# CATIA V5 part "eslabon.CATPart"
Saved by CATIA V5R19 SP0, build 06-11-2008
Part number: eslabon
Material "Dull Blue": density 7860 kg/m3, Young's modulus 2e+11 Pa, Poisson ratio 0.266
Bounding box of the stored display mesh (mm): x 189.734 to 215.134, y -352.1 to 352.1, z 11038.485 to 12155.485
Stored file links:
  E:\Luis\Dropbox\3DIT\Parking\planos\cat 3 dit park8\eslabon.CATPart
  E:\Luis\Dropbox\3DIT\Parking\planos\cat 3 dit park8\Eslabon de Cadena.........................................CATProduct
  E:\Luis\Dropbox\3DIT\Parking\planos\cat 3 dit park8\ensamble unico eslabon.CATProduct
  E:\Luis\Dropbox\3DIT\Parking\planos\cat 3 dit park8\Soportecuna.CATProduct
  E:\Luis\Dropbox\3DIT\Parking\planos\cat 3 dit park8\ensamble Parking3d.CATProduct
  C:\Program Files (x86)\Dassault Systemes\B19\intel_a\startup\materials\Catalog.CATMaterial
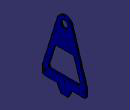
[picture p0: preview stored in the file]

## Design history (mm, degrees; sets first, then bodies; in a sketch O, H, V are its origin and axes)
External parameters (linked from other documents)
  External.P = 625
  External.b1 = 38.1
  External.b2 = 50.8
  External.d2 = 26.4
  External.g = 50.8
  External.LE = 800
Body1 (main body), material "Dull Blue"
  DatumSurface1
  DatumCurve1
  Sketch1, origin (410.9081, 7.5, 9247.3264), H (0, 1, 0), V (0, 0, 1), geometry linked from another document
  Sketch2, origin (410.9081, -1812.5, 6922.3264), H (0, 1, 0), V (0, 0, 1), geometry linked from another document
  Sketch3, origin (313.2342, -1812.5, 4597.3264), H (0, 1, 0), V (0, 0, 1), geometry linked from another document
  Sketch4 on DatumSurface4, origin (202.4342, 0, 0), H (0, 1, 0), V (0, 0, 1)
    point P2 (-312.5, 11235.4854)
    construction line L1 (0, 12035.4854) -> (0, 11235.4854)
    point P3 (0, 11235.4854)
    construction line L2 (0, 12035.4854) -> (-312.5, 11235.4854)
    line L3 (-114.5616, 12071.2016) -> (-352.1, 11309.2854)
    point P4 (-352.1, 11309.2854)
    circle A1 centre (0, 12035.4854) radius 60
    point P5 (0, 11869.2854)
    circle A2 centre (-312.5, 11235.4854) radius 13.2
    point P6 (-307.6972, 11247.7806)
    point P7 (487.5, 10734.2854)
    line L4 (-352.1, 11309.2854) -> (-352.1, 11176.963)
    point P8 (-352.1, 11072.4854)
    point P9 (-352.1, 11159.2854)
    circle A3 centre (0, 11235.4854) radius 9.525
    line L5 (-114.1377, 11159.2854) -> (-334.4223, 11159.2854)
    point P10 (-114.1377, 11159.2854)
    line L6 (-114.1377, 11159.2854) -> (-60, 11038.4854)
    point P11 (-60, 11038.4854)
    line L7 (-60, 11038.4854) -> (0, 11038.4854)
    point P12 (0, 11038.4854)
    line L8 (-352.1, 11176.963) -> (-334.4223, 11159.2854)
    point P13 (-352.1, 11176.963)
    point P14 (-334.4223, 11159.2854)
    construction line L9 (0, 11551.55) -> (0, 12155.4854)
    point P15 (0, 11551.55)
    arc A4 centre (0, 12035.4854) radius 120 from (0, 12155.4854) to (-114.5616, 12071.2016) ccw
    point P16 (0, 12035.4854)
    point P17 (0, 12155.4854)
    point P18 (0, 12155.4854)
    point P19 (-114.5616, 12071.2016)
    point P20 (114.5616, 12071.2016)
    point P21 (0, 12155.4854)
    arc A5 centre (0, 12035.4854) radius 120 from (0, 12155.4854) to (114.5616, 12071.2016) cw
    point P23 (352.1, 11309.2854)
    line L10 (114.5616, 12071.2016) -> (352.1, 11309.2854)
    point P24 (352.1, 11176.963)
    line L11 (352.1, 11309.2854) -> (352.1, 11176.963)
    point P25 (334.4223, 11159.2854)
    point P26 (114.1377, 11159.2854)
    line L12 (114.1377, 11159.2854) -> (334.4223, 11159.2854)
    point P27 (60, 11038.4854)
    line L13 (114.1377, 11159.2854) -> (60, 11038.4854)
    point P28 (0, 11038.4854)
    line L14 (60, 11038.4854) -> (0, 11038.4854)
    circle A6 centre (312.5, 11235.4854) radius 13.2
    line L15 (352.1, 11176.963) -> (334.4223, 11159.2854)
    radius A1 = 60
    radius A2 = 13.2 {= External.d2 /1000/2}
    length L1 = 800 {= External.LE /1000}
    distance P2 L4 = 39.6 {= External.d2 *1.5/1000}
    length L7 = 60
    distance P4 P9 = 150
    distance P10 P9 = 237.9623 (reference)
    angle L4 L8 = 45
    length L8 = 25
    angle L6 L5 = -294.14
    distance L1 P12 = 0
    radius A4 = 120
    distance L14 H = 11038.4854
    distance P11 V = 60 (reference)
    distance L5 P12 = 120.8
    distance P2 L5 = 76.2 {= External.g  *1.5/1000}
    distance L12 P3 = 76.2 {= External.g *1.5/1000}
    radius A3 = 9.525
    distance P2 L1 = 312.5 {= External.P /2/1000}
    vertical: L1 V, L4 V, L9 V
    coincidence: A2 P6, P6 L2, L4 P8, P12 V, L4 P9, L5 P9, P15 L1, L9 L1, P16 L2, P16 L1, L9 P17, P18 A4
    horizontal: L5 H
    tangency: A4 L3
    symmetry: P19 P20 L1, P17 P21 L1, A4 A5 L1, P4 P23 L1, L3 L10 L1, P13 P24 L1, L4 L11 L1, P14 P25 L1, P10 P26 L1, L5 L12 L1, P11 P27 L1, L6 L13 L1, P12 P28 L1, L7 L14 L1, A2 A6 L1, L8 L15 L1
  Pad1: profile Sketch4, direction (1, 0, 0), length 12.7, mirrored extent
  Sketch5, origin (253.2342, 7.5, 9247.3264), H (0, 1, 0), V (0, 0, 1), geometry linked from another document
  Sketch6, origin (253.2342, 7.5, 9247.3264), H (0, 1, 0), V (0, 0, 1), geometry linked from another document
  Sketch7 on start face of Pad1, origin (189.7342, 0, 0), H (0, -1, 0), V (0, 0, 1)
    line L1 (-121.4014, 11674.2854) -> (121.4014, 11674.2854)
    line L2 (164.362, 11642.6789) -> (254.7737, 11352.6789)
    line L3 (211.8131, 11294.2854) -> (-211.8131, 11294.2854)
    line L4 (-254.7737, 11352.6789) -> (-164.362, 11642.6789)
    arc A1 centre (121.4014, 11629.2854) radius 45 from (164.362, 11642.6789) to (121.4014, 11674.2854) ccw
    arc A2 centre (-121.4014, 11629.2854) radius 45 from (-164.362, 11642.6789) to (-121.4014, 11674.2854) cw
    arc A3 centre (-211.8131, 11339.2854) radius 45 from (-254.7737, 11352.6789) to (-211.8131, 11294.2854) ccw
    arc A4 centre (211.8131, 11339.2854) radius 45 from (211.8131, 11294.2854) to (254.7737, 11352.6789) ccw
    construction line L5 (-341.8007, 11342.3207) -> (-146.2032, 11969.7094)
    construction line L6 (-341.8007, 11342.3207) -> (-146.2032, 11969.7094)
    construction line L7 (-273.1, 11161.8476) -> (-273.1, 11259.2854)
    construction line L8 (0, 11038.4854) -> (-60, 11038.4854)
    construction arc A5 centre (0, 11809.2854) radius 120 from (111.9424, 11852.5162) to (-111.9424, 11852.5162) ccw
    point P13 (0, 11209.2854)
    reference projected line E1 (166.7596, 11903.7738) -> (346.5875, 11326.9671) from edge [start face of Pad1 | face of Pad1 from Sketch4.L3]
    reference projected line E2 (282.3223, 11159.2854) -> (114.1377, 11159.2854) from edge [start face of Pad1 | face of Pad1 from Sketch4.L5]
    reference projected line E3 (-351.7709, 11310.3409) -> (-164.0095, 11912.595) from edge [start face of Pad1 | face of Pad1 from Sketch4.L10]
    reference projected circle E4 centre (0, 12035.4854) radius 60 from edge [face of Pad1 from Sketch4.A1 | start face of Pad1]
    construction line L9 (0, 12035.4854) -> (0, 10925.82)
    point P14 (0, 12035.4854)
    distance L3 L1 = 380
    radius A1 = 45
    radius A2 = 45
    radius A3 = 45
    radius A4 = 45
    distance L8 A5 = 890.8 (reference)
    distance L2 E1 = 80
    distance L3 E2 = 135
    distance L4 L6 = 80
    horizontal: L1 H
    tangency: A1 L2, A1 L1, A2 L4, A2 L1, A3 L4, A3 L3, A4 L3, A4 L2
    coincidence: L6 L5, L6 E3
    concentricity: P14 E4
    vertical: L9 V
  Pocket1: profile Sketch7, direction (1, 0, 0), length 38.1
  Plane1: type Offset, Offset 12.7, RefPlane end face of Pad1, reversed
  Sketch8 on Plane1, origin (227.8342, 0, 0), H (0, -1, 0), V (0, 0, 1)
    reference projected circle E1 centre (312.5, 11235.4854) radius 13.2 from edge [face of Pad1 from Sketch4.A2 | start face of Pad1]
    point P1 (312.5, 11235.4854)
    point P2 (-529.21, 11479.88)
    reference projected circle E2 centre (-312.5, 11235.4854) radius 13.2 from edge [face of Pad1 from Sketch4.A6 | start face of Pad1]
    point P3 (-312.5, 11235.4854)
    concentricity: P1 E1, P3 E2
  Point1: stored without definition
  Sketch9, origin (253.2342, 7.5, 9247.3264), H (0, 1, 0), V (0, 0, 1), geometry linked from another document
  DatumCurve2
  DatumSurface2 to DatumSurface4
  Sketch10 on end face of Pad1, origin (215.1342, 0, 0), H (0, 1, 0), V (0, 0, 1)
    reference projected circle E1 centre (0, 12035.4854) radius 60 from edge [end face of Pad1 | face of Pad1 from Sketch4.A1]
    point P1 (0, 12035.4854)
    concentricity: P1 E1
